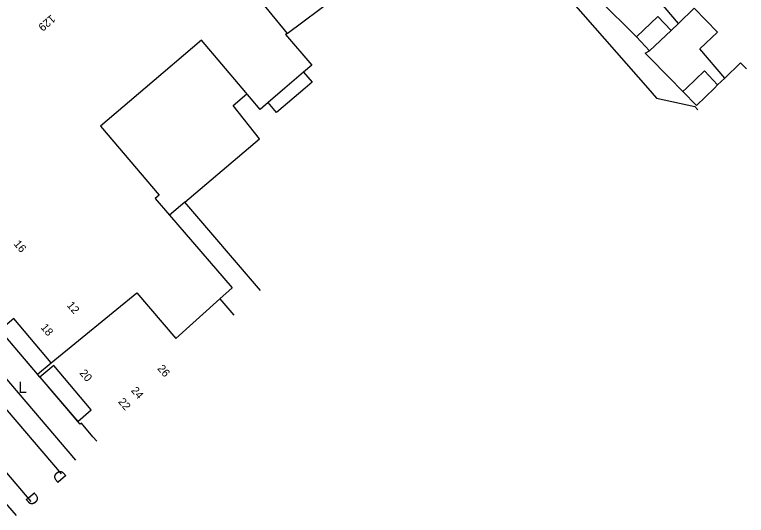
# Model space of a CAD drawing. Extents: x 81617 to 82144, y 454649 to 455150.
# Drawn here: x 81836.9 to 81900.9, y 454762.6 to 454806.4 of the extents above; entities that cross this region are included whole.
import ezdxf

# ---------------------------------------------------------------- set-up
doc = ezdxf.new("R2010")
doc.units = 0
doc.layers.add('B-WE-OG-TOPOGRAFIE-G', color=7, linetype='Continuous')

msp = doc.modelspace()

# ---------------------------------------------------------------- linework, layer by layer
at = {"layer": 'B-WE-OG-TOPOGRAFIE-G'}
for p, q in [((81860.759, 454804.784), (81869.009, 454810.93)), ((81894.349, 454805.024), (81894.977, 454805.656)), ((81862.19, 454801.388), (81860.571, 454800)), ((81899.022, 454800.855), (81898.397, 454800.275)), ((81860.571, 454800), (81859.088, 454798.728)), ((81895.372, 454799.699), (81895.075, 454800)), ((81851.811, 454790.028), (81850.463, 454788.89)), ((81822.76, 454787.622), (81840.998, 454766.241)), ((81838.37, 454763.823), (81819.99, 454785.382)), ((81838.943, 454774.955), (81835.644, 454778.819)), ((81838.292, 454775.714), (81835.644, 454778.819)), ((81838.943, 454774.955), (81840.128, 454775.958)), ((81838.943, 454774.955), (81838.292, 454775.714)), ((81839.148, 454774.717), (81838.943, 454774.955)), ((81839.148, 454774.717), (81842.457, 454770.831)), ((81839.801, 454773.951), (81839.148, 454774.717)), ((81841.995, 454771.374), (81839.801, 454773.951)), ((81842.457, 454770.831), (81841.995, 454771.374))]:
    msp.add_line(p, q, dxfattribs=at)
for points in [[(81900.915, 454801.668), (81900.406, 454802.194), (81899.022, 454800.855), (81896.86, 454803.422), (81898.383, 454804.874), (81896.361, 454806.995), (81894.977, 454805.656), (81892.815, 454808.223), (81894.199, 454809.562), (81892.304, 454811.818), (81890.92, 454810.479), (81890.103, 454811.416)], [(81856.206, 454810.339), (81860.759, 454804.784), (81860.623, 454804.682), (81862.915, 454802.01), (81862.19, 454801.388)], [(81891.32, 454804.491), (81888.026, 454807.766), (81888.336, 454808.106)], [(81885.76, 454807.421), (81892.287, 454800)], [(81894.349, 454805.024), (81892.445, 454803.258), (81891.32, 454804.491), (81893.184, 454806.264), (81894.349, 454805.024)], [(81856.816, 454800), (81853.266, 454804.196), (81848.353, 454800)], [(81895.075, 454800), (81894.466, 454800.618), (81892.066, 454803.05), (81892.445, 454803.258)], [(81862.19, 454801.388), (81862.935, 454800.52), (81862.329, 454800)], [(81895.688, 454800), (81897.255, 454801.49), (81898.397, 454800.275), (81898.119, 454800)], [(81848.353, 454800), (81844.445, 454796.662), (81849.582, 454790.613), (81849.233, 454790.323), (81850.463, 454788.89)], [(81859.088, 454798.728), (81858.396, 454798.134), (81856.816, 454800)], [(81862.329, 454800), (81859.838, 454797.862), (81859.088, 454798.728)], [(81892.287, 454800), (81893.064, 454799.117), (81896.396, 454798.381), (81896.659, 454798.097)], [(81898.119, 454800), (81896.565, 454798.461), (81895.372, 454799.699), (81895.688, 454800)], [(81851.811, 454790.028), (81858.356, 454795.548), (81856.028, 454798.466), (81857.244, 454799.495)], [(81858.432, 454782.279), (81851.811, 454790.028)], [(81850.463, 454788.89), (81855.944, 454782.51), (81854.864, 454781.543), (81856.084, 454780.119)], [(81842.296, 454767.435), (81829.229, 454782.739)], [(81840.128, 454775.958), (81847.623, 454782.079), (81851.028, 454778.093), (81854.864, 454781.543)], [(81840.128, 454775.958), (81836.85, 454779.832), (81835.644, 454778.819)], [(81842.457, 454770.831), (81843.637, 454771.836), (81840.347, 454775.722), (81839.148, 454774.717)], [(81844.111, 454769.104), (81843.781, 454769.49), (81842.767, 454770.679), (81842.662, 454770.593), (81842.457, 454770.831)], [(81835.737, 454764.161), (81837.056, 454762.614)]]:
    msp.add_lwpolyline(points, dxfattribs=at)

# ---------------------------------------------------------------- texts
for s, height, rotation, p in [('129', 0.7, 220.42801, (81840.124, 454806.456)), ('16', 0.7, 310.29077, (81836.809, 454786.338)), ('12', 0.7, 310.23636, (81841.455, 454780.971)), ('18', 0.7, 310.23636, (81839.165, 454779.033)), ('20', 0.7, 310.40008, (81842.567, 454775.033)), ('26', 0.7, 310.47796, (81849.369, 454775.439)), ('24', 0.7, 310.47796, (81847.065, 454773.516)), ('22', 0.7, 310.47796, (81845.936, 454772.53)), ('D', 1, 130.35482, (81841.541, 454765.996)), ('D', 1, 310.31413, (81837.815, 454764.083))]:
    msp.add_text(s, height=height, rotation=rotation, dxfattribs=at).set_placement(p)
msp.add_text('L', height=1, dxfattribs=at).set_placement((81837.261, 454773.316))

doc.saveas('drawing.dxf')
